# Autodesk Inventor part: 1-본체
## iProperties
Created: 2015-01
Part Number: 1-본체
Document SubType Name: Modeling
Designer: Administrator
Density: 2.71 g/cm^3
Material: 알루미늄-6061
Mass: 1021.35 g
Surface Area: 1059.8 cm^2
Volume: 376.881 cm^3
Author: Administrator
